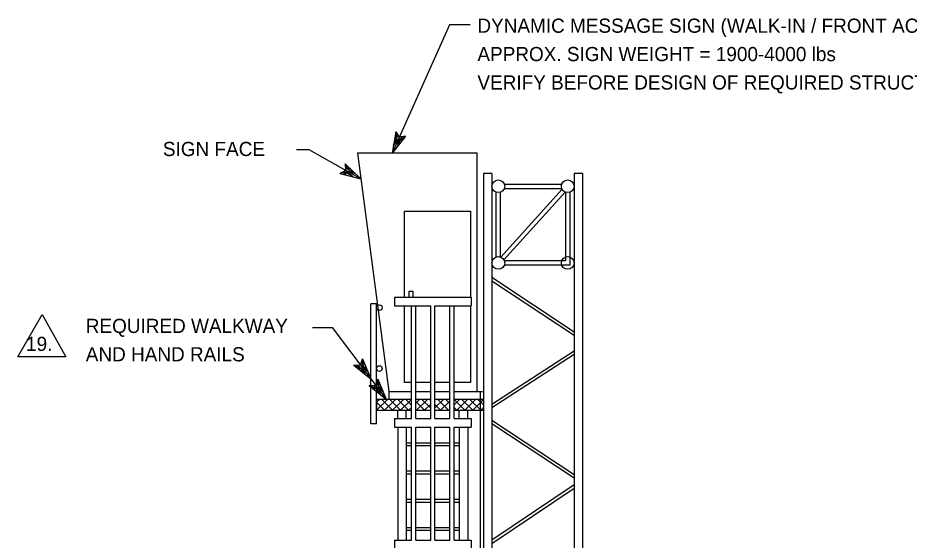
# Model space of a CAD drawing. Extents: x 515543 to 517243, y 661761 to 662861.
# Drawn here: x 516730.5 to 517056.7, y 662142.1 to 662333 of the extents above; entities that cross this region are included whole.
import ezdxf

# ---------------------------------------------------------------- set-up
doc = ezdxf.new("R2010")
doc.units = 0
for name, color, linetype in [('Level 8', 7, 'Continuous'), ('LTT', 7, 'Continuous'), ('SHT-BNDRY', 7, 'Continuous')]:
    doc.layers.add(name, color=color, linetype=linetype)

msp = doc.modelspace()

# ---------------------------------------------------------------- linework, layer by layer
at = {"layer": 'Level 8'}
for p, q in [((516904.01, 662276.09), (516904.01, 662091.76)), ((516937.19, 662276.09), (516937.19, 662013.03)), ((516907.25, 662245.62), (516929.69, 662270.36)), ((516908.4, 662244.58), (516930.84, 662269.31)), ((516934.08, 662218.19), (516904.01, 662238.1)), ((516934.08, 662216.95), (516904.01, 662236.85)), ((516868.34, 662230.9), (516896.39, 662230.9)), ((516868.34, 662230.9), (516868.34, 662227.79)), ((516896.39, 662230.9), (516896.39, 662227.79)), ((516868.34, 662227.79), (516875.89, 662227.79)), ((516874.57, 662186.54), (516874.57, 662227.79)), ((516875.89, 662227.79), (516881.59, 662227.79)), ((516876.13, 662186.54), (516876.13, 662227.79)), ((516881.59, 662186.54), (516881.59, 662227.79)), ((516883.14, 662227.79), (516896.39, 662227.79)), ((516883.14, 662186.54), (516883.14, 662227.79)), ((516888.6, 662186.54), (516888.6, 662227.79)), ((516890.15, 662186.54), (516890.15, 662227.79)), ((516934.08, 662211.22), (516904.01, 662191.75)), ((516934.08, 662209.99), (516904.01, 662190.52)), ((516899.74, 662196.46), (516899.74, 661976.89)), ((516861.78, 662192.54), (516862.93, 662193.69)), ((516861.78, 662189.61), (516865.86, 662193.69)), ((516861.78, 662193.69), (516866.34, 662193.69)), ((516861.78, 662192.54), (516864.71, 662189.61)), ((516863.56, 662193.69), (516867.65, 662189.61)), ((516864.71, 662189.61), (516868.8, 662193.69)), ((516866.5, 662193.69), (516870.58, 662189.61)), ((516867.65, 662189.61), (516871.73, 662193.69)), ((516869.43, 662193.69), (516873.51, 662189.61)), ((516870.58, 662189.61), (516874.66, 662193.69)), ((516872.36, 662193.69), (516874.57, 662191.48)), ((516876.13, 662192.23), (516877.59, 662193.69)), ((516876.13, 662192.86), (516879.38, 662189.61)), ((516876.44, 662189.61), (516880.53, 662193.69)), ((516878.23, 662193.69), (516881.59, 662190.33)), ((516879.38, 662189.61), (516881.59, 662191.82)), ((516881.16, 662193.69), (516881.59, 662193.26)), ((516883.14, 662190.44), (516886.39, 662193.69)), ((516883.14, 662193.37), (516883.46, 662193.69)), ((516883.14, 662191.71), (516885.24, 662189.61)), ((516884.09, 662193.69), (516888.17, 662189.61)), ((516885.24, 662189.61), (516888.6, 662192.96)), ((516887.02, 662193.69), (516888.6, 662192.12)), ((516890.15, 662191.59), (516892.26, 662193.69)), ((516890.15, 662193.5), (516894.04, 662189.61)), ((516891.11, 662189.61), (516895.19, 662193.69)), ((516892.89, 662193.69), (516896.97, 662189.61)), ((516894.04, 662189.61), (516898.12, 662193.69)), ((516895.82, 662193.69), (516899.9, 662189.61)), ((516896.97, 662189.61), (516900.9, 662193.54)), ((516898.75, 662193.69), (516900.9, 662191.54)), ((516861.78, 662189.61), (516861.78, 662189.61)), ((516869.55, 662186.54), (516869.55, 662189.61)), ((516872.66, 662186.54), (516872.66, 662189.61)), ((516873.51, 662189.61), (516874.57, 662190.67)), ((516876.13, 662189.92), (516876.44, 662189.61)), ((516888.17, 662189.61), (516888.6, 662190.03)), ((516890.15, 662190.56), (516891.11, 662189.61)), ((516892.06, 662186.54), (516892.06, 662189.61)), ((516895.17, 662186.54), (516895.17, 662189.61)), ((516899.9, 662189.61), (516900.9, 662190.61)), ((516868.34, 662186.54), (516868.34, 662183.43)), ((516868.34, 662186.54), (516874.57, 662186.54)), ((516876.13, 662186.54), (516881.59, 662186.54)), ((516883.14, 662186.54), (516888.6, 662186.54)), ((516890.15, 662186.54), (516896.39, 662186.54)), ((516896.39, 662186.54), (516896.39, 662183.43)), ((516904.01, 662186), (516934.08, 662166.14)), ((516868.34, 662183.43), (516874.57, 662183.43)), ((516869.55, 662183.43), (516869.55, 662142.18)), ((516872.66, 662183.43), (516872.66, 662142.18)), ((516874.57, 662142.18), (516874.57, 662183.43)), ((516876.13, 662183.43), (516881.59, 662183.43)), ((516876.13, 662142.18), (516876.13, 662183.43)), ((516881.59, 662142.18), (516881.59, 662183.43)), ((516883.14, 662183.43), (516888.6, 662183.43)), ((516883.14, 662142.18), (516883.14, 662183.43)), ((516888.6, 662142.18), (516888.6, 662183.43)), ((516890.15, 662183.43), (516896.39, 662183.43)), ((516890.15, 662142.18), (516890.15, 662183.43)), ((516892.06, 662183.43), (516892.06, 662142.18)), ((516895.17, 662183.43), (516895.17, 662142.18)), ((516904.01, 662184.76), (516934.08, 662164.89)), ((516872.66, 662177.73), (516874.57, 662177.73)), ((516872.66, 662176.69), (516874.57, 662176.69)), ((516876.13, 662177.73), (516881.59, 662177.73)), ((516876.13, 662176.69), (516881.59, 662176.69)), ((516883.14, 662177.73), (516888.6, 662177.73)), ((516883.14, 662176.69), (516888.6, 662176.69)), ((516890.15, 662177.73), (516892.06, 662177.73)), ((516890.15, 662176.69), (516892.06, 662176.69)), ((516872.66, 662167.41), (516874.57, 662167.41)), ((516872.66, 662166.38), (516874.57, 662166.38)), ((516876.13, 662167.41), (516881.59, 662167.41)), ((516876.13, 662166.38), (516881.59, 662166.38)), ((516883.14, 662167.41), (516888.6, 662167.41)), ((516883.14, 662166.38), (516888.6, 662166.38)), ((516890.15, 662167.41), (516892.06, 662167.41)), ((516890.15, 662166.38), (516892.06, 662166.38)), ((516904.01, 662142.19), (516934.08, 662162.42)), ((516904.01, 662140.94), (516934.08, 662161.17)), ((516872.66, 662157.1), (516874.57, 662157.1)), ((516872.66, 662156.07), (516874.57, 662156.07)), ((516876.13, 662157.1), (516881.59, 662157.1)), ((516876.13, 662156.07), (516881.59, 662156.07)), ((516883.14, 662157.1), (516888.6, 662157.1)), ((516883.14, 662156.07), (516888.6, 662156.07)), ((516890.15, 662157.1), (516892.06, 662157.1)), ((516890.15, 662156.07), (516892.06, 662156.07)), ((516872.66, 662146.79), (516874.57, 662146.79)), ((516876.13, 662146.79), (516881.59, 662146.79)), ((516883.14, 662146.79), (516888.6, 662146.79)), ((516890.15, 662146.79), (516892.06, 662146.79)), ((516872.66, 662145.75), (516874.57, 662145.75)), ((516876.13, 662145.75), (516881.59, 662145.75)), ((516883.14, 662145.75), (516888.6, 662145.75)), ((516890.15, 662145.75), (516892.06, 662145.75)), ((516868.34, 662142.18), (516868.34, 662139.07)), ((516868.34, 662142.18), (516874.57, 662142.18)), ((516876.13, 662142.18), (516881.59, 662142.18)), ((516883.14, 662142.18), (516888.6, 662142.18)), ((516890.15, 662142.18), (516896.39, 662142.18)), ((516896.39, 662142.18), (516896.39, 662139.07)), ((516896.39, 662142.18), (516896.39, 662139.07))]:
    msp.add_line(p, q, dxfattribs=at)
for points in [[(516896.08, 662330.47), (516888.54, 662330.47), (516867.49, 662283.58)], [(516832.55, 662284.96), (516836.95, 662284.96), (516856.01, 662274.15)], [(516898.63, 662196.46), (516898.63, 662283.58), (516854.76, 662283.58), (516866.34, 662196.46), (516874.57, 662196.46)], [(516904.01, 662276.09), (516900.9, 662276.09), (516900.9, 662013.03)], [(516937.19, 662276.09), (516934.08, 662276.09), (516934.08, 662091.76)], [(516908.54, 662272.24), (516929.55, 662272.24)], [(516908.54, 662270.69), (516929.55, 662270.69)], [(516905.57, 662245.67), (516905.57, 662269.27)], [(516907.12, 662245.67), (516907.12, 662269.27)], [(516930.97, 662269.27), (516930.97, 662244.25), (516908.54, 662244.25)], [(516932.52, 662269.27), (516932.52, 662242.69), (516908.54, 662242.69)], [(516871.99, 662230.9), (516871.99, 662262.32), (516896.19, 662262.32), (516896.19, 662230.9)], [(516873.71, 662230.9), (516873.71, 662233.12), (516875.04, 662233.12), (516875.04, 662230.9)], [(516861.78, 662184.59), (516859.71, 662184.59), (516859.71, 662228.53)], [(516861.78, 662184.59), (516861.78, 662228.53), (516859.71, 662228.53)], [(516874.57, 662199.74), (516871.99, 662199.74), (516871.99, 662227.79)], [(516896.19, 662227.79), (516896.19, 662199.74), (516890.15, 662199.74)], [(516838.36, 662219.88), (516845.58, 662219.88), (516865.33, 662193.69)], [(516881.59, 662199.74), (516876.13, 662199.74)], [(516888.6, 662199.74), (516883.14, 662199.74)], [(516866.34, 662196.46), (516866.34, 662193.69), (516874.57, 662193.69)], [(516876.13, 662196.46), (516881.59, 662196.46)], [(516883.14, 662196.46), (516888.6, 662196.46)], [(516890.15, 662196.46), (516900.52, 662196.46)], [(516861.78, 662193.69), (516861.78, 662189.61), (516874.57, 662189.61)], [(516876.13, 662193.69), (516881.59, 662193.69)], [(516883.14, 662193.69), (516888.6, 662193.69)], [(516890.15, 662193.69), (516900.9, 662193.69)], [(516876.13, 662189.61), (516881.59, 662189.61)], [(516883.14, 662189.61), (516888.6, 662189.61)], [(516890.15, 662189.61), (516900.9, 662189.61)]]:
    msp.add_lwpolyline(points, dxfattribs=at)
for centre, radius in [((516906.34, 662271.47), 2.33), ((516931.75, 662271.47), 2.33), ((516906.34, 662243.47), 2.33), ((516931.75, 662243.47), 2.33), ((516862.82, 662227.1), 1.04), ((516862.82, 662204.86), 1.04)]:
    msp.add_circle(centre, radius, dxfattribs=at)
at = {"layer": 'LTT'}
for points in [[(516868.81, 662291.37), (516867.49, 662283.58)], [(516872.44, 662289.74), (516867.49, 662283.58)], [(516870.07, 662289.31), (516868.04, 662286.47), (516869.62, 662289.99), (516868.54, 662289.1), (516869.08, 662290.3), (516868.81, 662291.37), (516870.12, 662289.42)], [(516870.07, 662289.31), (516869.29, 662285.91), (516870.87, 662289.42), (516870.93, 662288.03), (516871.46, 662289.23), (516872.44, 662289.74), (516870.12, 662289.42)], [(516850.54, 662277.25), (516853.18, 662274.97), (516849.83, 662276.87), (516850.6, 662275.72), (516849.47, 662276.36), (516848.37, 662276.19), (516850.44, 662277.31)], [(516850.54, 662277.25), (516853.86, 662276.16), (516850.5, 662278.06), (516851.89, 662277.99), (516850.75, 662278.63), (516850.33, 662279.66), (516850.44, 662277.31)], [(516850.33, 662279.66), (516856.01, 662274.15)], [(516848.37, 662276.19), (516856.01, 662274.15)], [(516855.93, 662206.16), (516858.53, 662203.84), (516856.21, 662206.92), (516857.46, 662206.3), (516856.67, 662207.34), (516856.69, 662208.45), (516855.85, 662206.26)], [(516856.69, 662208.45), (516859.71, 662201.14)], [(516855.93, 662206.16), (516857.44, 662203.02), (516855.12, 662206.1), (516855.37, 662204.73), (516854.58, 662205.77), (516853.51, 662206.06), (516855.85, 662206.26)], [(516853.51, 662206.06), (516859.71, 662201.14)], [(516861.54, 662198.71), (516863.06, 662195.56), (516860.74, 662198.64), (516860.99, 662197.28), (516860.2, 662198.32), (516859.13, 662198.6), (516861.47, 662198.81)], [(516859.13, 662198.6), (516865.33, 662193.69)], [(516861.54, 662198.71), (516864.15, 662196.39), (516861.83, 662199.47), (516863.07, 662198.85), (516862.29, 662199.89), (516862.31, 662201), (516861.47, 662198.81)], [(516862.31, 662201), (516865.33, 662193.69)]]:
    msp.add_lwpolyline(points, dxfattribs=at)
at = {"layer": 'SHT-BNDRY'}
msp.add_lwpolyline([(516730.52, 662209.15), (516739.43, 662224.57), (516748.14, 662209.15)], close=True, dxfattribs=at)

# ---------------------------------------------------------------- texts
at = {"layer": 'Level 8'}
for s, p in [('DYNAMIC MESSAGE SIGN (WALK-IN / FRONT ACCESS)', (516898.69, 662327.58)), ('APPROX. SIGN WEIGHT = 1900-4000 lbs', (516898.69, 662317.21)), ('VERIFY BEFORE DESIGN OF REQUIRED STRUCTURE', (516898.69, 662306.84)), ('SIGN FACE', (516783.61, 662282.52)), ('REQUIRED WALKWAY', (516755.39, 662217.84)), ('19.', (516733.53, 662211.27)), ('AND HAND RAILS', (516755.39, 662207.47))]:
    msp.add_text(s, height=5.184, rotation=360, dxfattribs=at).set_placement(p)

doc.saveas('drawing.dxf')
